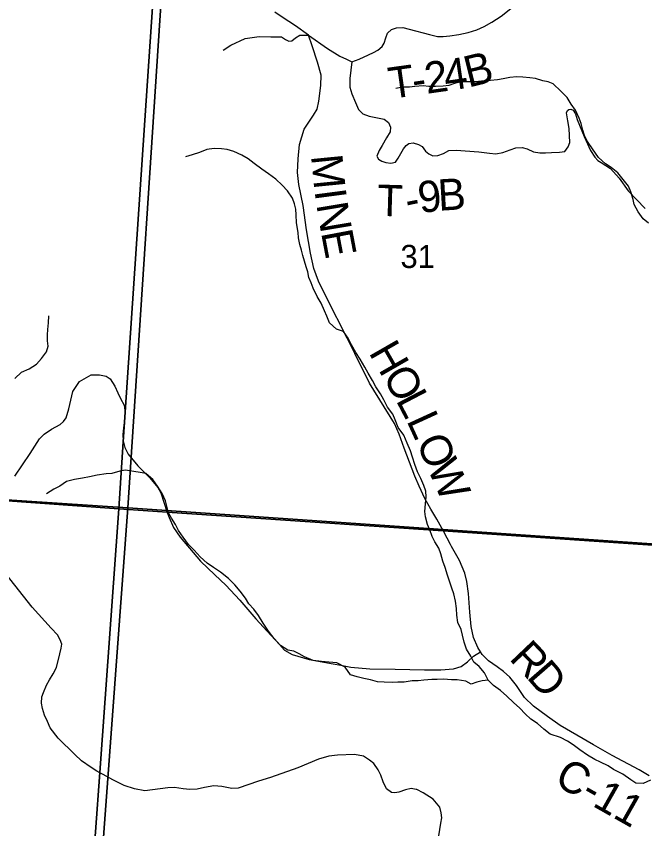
# Model space of a CAD drawing. Extents: x 0 to 34, y 0 to 22.
# Drawn here: x 5.215 to 6.354, y 18.398 to 19.87 of the extents above; entities that cross this region are included whole.
import ezdxf

# ---------------------------------------------------------------- set-up
doc = ezdxf.new("R2010")
doc.units = 0
for name, color, linetype in [('GM_X_County_Road', 7, 'Continuous'), ('GM_X_County_Road_Text', 7, 'Continuous'), ('GM_X_Minor_River', 7, 'Continuous'), ('GM_X_Section', 7, 'Continuous'), ('GM_X_Section_Text', 7, 'Continuous'), ('GM_X_Township_Road', 7, 'Continuous'), ('GM_X_Township_Road_Text', 7, 'Continuous'), ('SC_Scratch1', 7, 'Continuous')]:
    doc.layers.add(name, color=color, linetype=linetype)

msp = doc.modelspace()

# ---------------------------------------------------------------- linework, layer by layer
at = {"layer": 'GM_X_County_Road'}
for points in [[(6.004, 18.9092), (6.0019, 18.9128), (5.9897, 18.936), (5.9891, 18.9372), (5.9772, 18.959), (5.9665, 18.9773), (5.9554, 18.9966), (5.945, 19.0186), (5.9377, 19.0366), (5.9181, 19.0877), (5.909, 19.1128), (5.9007, 19.1324), (5.8554, 19.2052), (5.8285, 19.2593), (5.815, 19.2872), (5.7777, 19.3593), (5.7627, 19.3902), (5.7542, 19.4132), (5.748, 19.4412), (5.7413, 19.4832), (5.7352, 19.5276), (5.7273, 19.5658), (5.7249, 19.5875), (5.726, 19.6123), (5.7281, 19.6381), (5.7324, 19.6521), (5.7368, 19.6661), (5.7441, 19.677), (5.7536, 19.6912), (5.7603, 19.7022), (5.7631, 19.7163), (5.767, 19.7447), (5.7679, 19.7637), (5.7609, 19.7873), (5.7511, 19.8166), (5.7444, 19.8362), (5.7211, 19.853), (5.6967, 19.8686), (5.6838, 19.8781)], [(6.362, 18.4937), (6.3442, 18.5044), (6.2953, 18.5307), (6.2616, 18.5497), (6.2008, 18.5852), (6.1781, 18.6011), (6.1527, 18.62), (6.1365, 18.6359), (6.1215, 18.6577), (6.1096, 18.6727), (6.0983, 18.6831), (6.0867, 18.6916), (6.0711, 18.7023), (6.0594, 18.7136), (6.0565, 18.7184), (6.0515, 18.7265), (6.0438, 18.7442), (6.0396, 18.7647), (6.0371, 18.7907), (6.0347, 18.8244), (6.0319, 18.8458), (6.0279, 18.8611), (6.0181, 18.884), (6.004, 18.9092)]]:
    msp.add_lwpolyline(points, dxfattribs=at)
at = {"layer": 'GM_X_Minor_River'}
for points in [[(6.2136, 19.7235), (6.2018, 19.7348), (6.1885, 19.7477), (6.179, 19.7515), (6.1692, 19.7537), (6.1563, 19.7579), (6.1457, 19.7586), (6.1332, 19.7601), (6.1226, 19.7608), (6.1097, 19.7596), (6.0976, 19.757), (6.0874, 19.7554), (6.0745, 19.7542), (6.0636, 19.7535), (6.0526, 19.7523), (6.0424, 19.7519), (6.0318, 19.7515), (6.0216, 19.7515), (6.0095, 19.7488), (5.9989, 19.745), (5.9887, 19.7438), (5.975, 19.7434), (5.9625, 19.7434), (5.9523, 19.7441), (5.9376, 19.7429), (5.9277, 19.7418), (5.9152, 19.7417), (5.9027, 19.7398)], [(6.3608, 19.4953), (6.3513, 19.5032), (6.3422, 19.5157), (6.3349, 19.529), (6.333, 19.5384), (6.3288, 19.5525), (6.3246, 19.5623), (6.3151, 19.5744), (6.3052, 19.5865), (6.2931, 19.5963), (6.2832, 19.6031), (6.2703, 19.6145), (6.2593, 19.63), (6.2505, 19.6432), (6.2452, 19.6546), (6.2422, 19.6641), (6.2391, 19.6762), (6.2356, 19.686), (6.2284, 19.7004), (6.2208, 19.7114), (6.2136, 19.7235)], [(5.8879, 19.1617), (5.8811, 19.1753), (5.875, 19.1859), (5.867, 19.1991), (5.8609, 19.2101), (5.8529, 19.2234), (5.8468, 19.2347), (5.8384, 19.2487), (5.8305, 19.2612), (5.8225, 19.2752), (5.8167, 19.2873), (5.808, 19.2991), (5.7955, 19.3036), (5.7826, 19.3146), (5.7776, 19.3267), (5.7738, 19.3365), (5.7673, 19.3505), (5.7601, 19.3626), (5.7529, 19.3778), (5.7494, 19.3873), (5.7452, 19.3971), (5.7433, 19.407), (5.7406, 19.4164), (5.7372, 19.4263), (5.7345, 19.4369), (5.7318, 19.4464), (5.7291, 19.457), (5.7268, 19.4687), (5.726, 19.4786), (5.723, 19.496), (5.7222, 19.5108), (5.7214, 19.5206), (5.7191, 19.5305), (5.7156, 19.5407), (5.7065, 19.554), (5.6966, 19.5645), (5.6856, 19.5755), (5.6719, 19.5846), (5.6598, 19.5933), (5.6461, 19.6035), (5.6355, 19.6118), (5.6238, 19.6186), (5.6094, 19.6254), (5.5972, 19.6287), (5.587, 19.6302), (5.5734, 19.631), (5.5605, 19.629), (5.5469, 19.6233), (5.5337, 19.6195), (5.5216, 19.6157)], [(5.2125, 19.2142), (5.2245, 19.2252), (5.2381, 19.2313), (5.2514, 19.2397), (5.2608, 19.2503), (5.2695, 19.2625), (5.2728, 19.2727), (5.2717, 19.2822), (5.2716, 19.2928), (5.272, 19.3027), (5.2735, 19.3148), (5.2738, 19.3277)], [(6.3648, 18.4857), (6.3516, 18.48), (6.3383, 18.4807), (6.3288, 18.4867), (6.3148, 18.4966), (6.2974, 18.5052), (6.2879, 18.512), (6.2739, 18.5185), (6.2636, 18.5234), (6.2503, 18.5313), (6.2363, 18.5407), (6.2242, 18.5498), (6.2143, 18.5566), (6.2014, 18.563), (6.1828, 18.5694), (6.1715, 18.5781), (6.1597, 18.5887), (6.1475, 18.5966), (6.1377, 18.6061), (6.1278, 18.6163), (6.1164, 18.6269), (6.1039, 18.6379), (6.0925, 18.6484), (6.0803, 18.6575), (6.0701, 18.667), (6.0636, 18.6806), (6.0541, 18.6919), (6.0446, 18.6999), (6.0389, 18.7109), (6.0313, 18.7234), (6.0267, 18.7362), (6.0236, 18.7487), (6.0213, 18.759), (6.0152, 18.7719), (6.0137, 18.7851), (6.0129, 18.7972), (6.011, 18.8101), (6.0079, 18.8234), (6.0044, 18.8336), (5.9964, 18.8575), (5.9922, 18.8715), (5.9884, 18.8829), (5.9846, 18.8961), (5.9807, 18.9064), (5.9739, 18.9177), (5.9689, 18.9276), (5.9644, 18.9397), (5.9605, 18.9495), (5.9567, 18.9632), (5.9555, 18.973), (5.9566, 18.9867), (5.9581, 18.9996), (5.9573, 19.0098), (5.9539, 19.02), (5.9482, 19.0325), (5.9424, 19.0446), (5.9375, 19.0583), (5.9333, 19.0712), (5.9298, 19.0829), (5.9237, 19.0965), (5.9172, 19.1113), (5.907, 19.1249), (5.902, 19.1393), (5.8974, 19.1492), (5.8879, 19.1617)], [(6.0701, 18.667), (6.0595, 18.6662), (6.0497, 18.6635), (6.0395, 18.6601), (6.0296, 18.6653), (6.0141, 18.6676), (6.0038, 18.6679), (5.9891, 18.6687), (5.9781, 18.6686), (5.9683, 18.6682), (5.9539, 18.6671), (5.9433, 18.6659), (5.9327, 18.6659), (5.9183, 18.6636), (5.9066, 18.6635), (5.8964, 18.6627), (5.882, 18.6635), (5.8699, 18.6642), (5.857, 18.6676), (5.8449, 18.6702), (5.8327, 18.6732), (5.8206, 18.677), (5.8111, 18.691), (5.7959, 18.6985), (5.7812, 18.6996), (5.7683, 18.7011), (5.7528, 18.703), (5.7376, 18.7094), (5.7277, 18.7146), (5.7183, 18.7199), (5.7069, 18.7214), (5.694, 18.7297), (5.6826, 18.7426), (5.6723, 18.7562), (5.6625, 18.7702), (5.6541, 18.7842), (5.6457, 18.7956), (5.6362, 18.8058), (5.6305, 18.8156), (5.6206, 18.8285), (5.6111, 18.8402), (5.5997, 18.8516), (5.5853, 18.8629), (5.5724, 18.8716), (5.5607, 18.8792), (5.5485, 18.8905), (5.5375, 18.903), (5.5272, 18.9128), (5.5174, 18.9261), (5.509, 18.9382), (5.5036, 18.9492), (5.496, 18.9605), (5.4907, 18.9707), (5.4884, 18.9802), (5.4853, 18.992), (5.4796, 19.0052), (5.4709, 19.0185), (5.4625, 19.0309), (5.45, 19.0419), (5.4397, 19.0438), (5.428, 19.0456), (5.4129, 19.0475), (5.4023, 19.046), (5.3883, 19.0418), (5.3777, 19.0414), (5.3618, 19.0387), (5.3474, 19.0356), (5.3349, 19.0333), (5.3202, 19.0306), (5.3058, 19.0275), (5.2937, 19.0188), (5.2828, 19.0134), (5.2699, 19.0051)]]:
    msp.add_lwpolyline(points, dxfattribs=at)
at = {"layer": 'GM_X_Section'}
for points in [[(4.4687, 20.0485), (5.483, 19.983), (5.4174, 18.9797), (4.4009, 19.0464)], [(6.465, 19.9265), (6.4104, 18.9115), (5.4174, 18.9797), (5.483, 19.983)], [(4.3808, 19.0475), (4.4009, 19.0464), (5.4174, 18.9797), (5.3412, 17.9492), (4.3187, 18.0057)], [(5.4174, 18.9797), (6.4104, 18.9115), (6.3391, 17.8836), (5.3412, 17.9492)]]:
    msp.add_lwpolyline(points, close=True, dxfattribs=at)
at = {"layer": 'GM_X_Township_Road'}
for points in [[(5.823, 19.7879), (5.8362, 19.7928), (5.8536, 19.8007), (5.8625, 19.805), (5.8704, 19.8093), (5.8784, 19.8154), (5.882, 19.8218), (5.8848, 19.8313), (5.8878, 19.8396), (5.8952, 19.8463), (5.9044, 19.8494), (5.9154, 19.85), (5.927, 19.8472), (5.964, 19.8377), (5.9787, 19.8338), (5.9885, 19.8335), (6.0007, 19.835), (6.0172, 19.8377), (6.0338, 19.8408), (6.0497, 19.8457), (6.0631, 19.8521), (6.0772, 19.8598), (6.094, 19.8705), (6.1114, 19.8845)], [(5.5899, 19.8091), (5.604, 19.818), (5.6301, 19.83), (5.655, 19.8336), (5.6765, 19.833), (5.6955, 19.8333), (5.7031, 19.8283), (5.7087, 19.8254), (5.7146, 19.826), (5.721, 19.8312), (5.7287, 19.8364), (5.7444, 19.8362)], [(5.7444, 19.8362), (5.7793, 19.8123), (5.8016, 19.798), (5.8138, 19.7925), (5.823, 19.7879), (5.8193, 19.7576), (5.8193, 19.7417), (5.8233, 19.7301), (5.8297, 19.7142), (5.8355, 19.7013), (5.8429, 19.6934), (5.8548, 19.6894), (5.8698, 19.6866), (5.882, 19.6839), (5.8894, 19.6781), (5.893, 19.6695), (5.8927, 19.6609), (5.886, 19.6499), (5.8781, 19.6365), (5.8726, 19.6273), (5.8688, 19.617), (5.8716, 19.6117), (5.8778, 19.608), (5.8851, 19.6056), (5.8937, 19.604), (5.9025, 19.6062), (5.9071, 19.6131), (5.912, 19.6217), (5.9169, 19.6303), (5.9215, 19.6365), (5.9267, 19.6398), (5.9343, 19.6411), (5.9441, 19.638), (5.9506, 19.6343), (5.957, 19.6261), (5.9628, 19.6212), (5.9698, 19.6175), (5.979, 19.6184), (5.9891, 19.6218), (5.9989, 19.627), (6.0123, 19.6279), (6.0536, 19.6248), (6.0726, 19.6221), (6.0843, 19.6211), (6.0971, 19.6236), (6.1105, 19.6282), (6.1206, 19.6322), (6.1322, 19.6328), (6.1411, 19.63), (6.1524, 19.6248), (6.1641, 19.623), (6.1745, 19.623), (6.1849, 19.6236), (6.1995, 19.6239), (6.2094, 19.6255), (6.2154, 19.6337), (6.2185, 19.6417), (6.2173, 19.6671), (6.2145, 19.6808), (6.2124, 19.6952), (6.2142, 19.6995), (6.2167, 19.7016), (6.2204, 19.7022), (6.2243, 19.7001), (6.2286, 19.6934), (6.2317, 19.6836), (6.2445, 19.6527), (6.2561, 19.6273), (6.2638, 19.6151), (6.269, 19.6092), (6.2751, 19.6053), (6.2919, 19.5943), (6.3078, 19.5768), (6.3243, 19.5542), (6.3549, 19.5218)], [(5.212, 19.037), (5.2403, 19.0778), (5.2569, 19.1043), (5.2656, 19.113), (5.2786, 19.1222), (5.2943, 19.1308), (5.3004, 19.1357), (5.3051, 19.1429), (5.3103, 19.1588), (5.3154, 19.1824), (5.3174, 19.1905), (5.3293, 19.2084), (5.3507, 19.2203), (5.3659, 19.2207), (5.3779, 19.2184), (5.3852, 19.2131), (5.3937, 19.2001), (5.3991, 19.1878), (5.4041, 19.1779), (5.4106, 19.1658), (5.4118, 19.1564), (5.4115, 19.1424), (5.4094, 19.1245), (5.4081, 19.1126), (5.4085, 19.1002), (5.4091, 19.0984), (5.4119, 19.0888), (5.4175, 19.0769), (5.4355, 19.0558), (5.4568, 19.0338), (5.4716, 19.0161), (5.4768, 19.0067), (5.4887, 18.9713), (5.4918, 18.9622), (5.5001, 18.9438), (5.5122, 18.9266), (5.5486, 18.883), (5.5751, 18.8581), (5.595, 18.8395), (5.6202, 18.8123), (5.6493, 18.7785), (5.67, 18.7562), (5.692, 18.7316), (5.7012, 18.7217), (5.7148, 18.7138), (5.7458, 18.7044), (5.7893, 18.6966), (5.8031, 18.6941)], [(5.5563, 18.4727), (5.5428, 18.4697), (5.5294, 18.4689), (5.5176, 18.4704), (5.5016, 18.4724), (5.4899, 18.4718), (5.4479, 18.4663), (5.4289, 18.4699), (5.4107, 18.4765), (5.39, 18.4864), (5.3725, 18.4961), (5.3664, 18.4994), (5.3609, 18.5023), (5.3507, 18.5086), (5.3334, 18.5211), (5.3212, 18.5323), (5.2905, 18.5622), (5.2762, 18.5806), (5.2713, 18.5924), (5.2658, 18.6039), (5.2622, 18.6155), (5.2603, 18.6256), (5.2614, 18.6368), (5.2643, 18.6449), (5.2696, 18.6579), (5.2751, 18.6676), (5.2817, 18.6786), (5.2879, 18.6903), (5.294, 18.715), (5.2965, 18.7249), (5.2973, 18.7323), (5.2946, 18.7405), (5.2893, 18.7492), (5.2783, 18.7612), (5.2439, 18.7997), (5.1968, 18.8592)], [(5.8031, 18.6941), (5.8214, 18.6907), (5.8558, 18.6878), (5.902, 18.6871), (5.955, 18.686), (5.9848, 18.6858), (6.0077, 18.6876), (6.0214, 18.6921), (6.0326, 18.7006), (6.0438, 18.7105), (6.0565, 18.7184)], [(5.9397, 18.4689), (5.9308, 18.4708), (5.9207, 18.4682), (5.9087, 18.4642), (5.9014, 18.463), (5.8949, 18.4638), (5.886, 18.4699), (5.8801, 18.4826), (5.8759, 18.4951), (5.871, 18.5046), (5.8632, 18.516), (5.8554, 18.5223), (5.8444, 18.5293), (5.8281, 18.5325), (5.7975, 18.531), (5.7815, 18.5295), (5.7626, 18.5238), (5.725, 18.508), (5.676, 18.4908), (5.6541, 18.4843), (5.6173, 18.4716), (5.6059, 18.4706), (5.5875, 18.4742), (5.5732, 18.4754), (5.5563, 18.4727)], [(5.9811, 18.3852), (5.9844, 18.408), (5.9863, 18.4176), (5.9853, 18.4264), (5.9825, 18.437), (5.9709, 18.4516), (5.9526, 18.4632), (5.9409, 18.4687), (5.9397, 18.4689)]]:
    msp.add_lwpolyline(points, dxfattribs=at)
at = {"layer": 'SC_Scratch1'}
for points in [[(5.53, 20.9), (2.1, 20.9), (2.1, 19.1982), (2.3572, 19.1804), (3.3448, 19.1146), (4.3628, 19.0495), (4.7394, 19.0241), (4.7997, 19.0196), (5.182, 18.9932), (5.4007, 18.9779), (5.4089, 19.0989), (5.4469, 19.6641), (5.4955, 20.3864)], [(8.9, 18.7389), (8.9, 20.9), (5.53, 20.9), (5.4955, 20.3864), (5.4469, 19.6641), (5.4089, 19.0989), (5.4007, 18.9779), (5.4885, 18.9719), (5.9889, 18.9377), (6.8273, 18.8804), (7.2159, 18.8539), (8.2061, 18.7863)], [(2.1, 19.1982), (2.1, 14.1), (5.0535, 14.1), (5.0814, 14.5016), (5.1049, 14.8414), (5.1794, 15.9156), (5.2761, 17.2534), (5.2869, 17.4026), (5.3506, 18.2846), (5.3662, 18.4999), (5.4007, 18.9779), (5.182, 18.9932), (4.7997, 19.0196), (4.7394, 19.0241), (4.3628, 19.0495), (3.3448, 19.1146), (2.3572, 19.1804)], [(5.0535, 14.1), (8.9, 14.1), (8.9, 18.7389), (8.2061, 18.7863), (7.2159, 18.8539), (6.8273, 18.8804), (5.9889, 18.9377), (5.4885, 18.9719), (5.4007, 18.9779), (5.3662, 18.4999), (5.3506, 18.2846), (5.2869, 17.4026), (5.2761, 17.2534), (5.1794, 15.9156), (5.1049, 14.8414), (5.0814, 14.5016)]]:
    msp.add_lwpolyline(points, close=True, dxfattribs=at)

# ---------------------------------------------------------------- texts
at = {"layer": 'GM_X_County_Road_Text'}
for s, height, rotation, p in [('M', 0.0568, 275.6268, (5.7491, 19.6178)), ('I', 0.0568, 277.4871, (5.7554, 19.5545)), ('N', 0.0568, 279.4602, (5.7587, 19.5293)), ('E', 0.0568, 280.7354, (5.7672, 19.4786)), ('H', 0.0568, 299.8741, (5.8529, 19.2611)), ('O', 0.0568, 299.763, (5.8778, 19.2177)), ('L', 0.0568, 297.6096, (5.9023, 19.1748)), ('L', 0.0568, 294.5944, (5.9217, 19.1379)), ('O', 0.0568, 293.0489, (5.9392, 19.0996)), ('W', 0.0568, 293.7523, (5.9591, 19.0529)), ('R', 0.0568, 313.6254, (6.1068, 18.7054)), ('D', 0.0568, 310.968, (6.1386, 18.6721)), ('C-11', 0.05682, 330.5374, (6.1877, 18.4795))]:
    msp.add_text(s, height=height, rotation=rotation, dxfattribs=at).set_placement(p)
at = {"layer": 'GM_X_Section_Text'}
msp.add_text('31', height=0.04186, rotation=0, dxfattribs=at).set_placement((5.9114, 19.4142))
at = {"layer": 'GM_X_Township_Road_Text'}
for s, rotation, p in [('4', 8.2578, (5.9938, 19.7347)), ('B', 13.874, (6.0344, 19.7409)), ('T', 8.001, (5.8937, 19.7206)), ('2', 8.0642, (5.959, 19.7298)), ('-', 8.0129, (5.9358, 19.7265)), ('9', 7.6995, (5.947, 19.5133)), ('B', 3.3509, (5.9806, 19.5179)), ('T', 358.307, (5.8684, 19.5088)), ('-', 11.651, (5.9252, 19.5088))]:
    msp.add_text(s, height=0.0568, rotation=rotation, dxfattribs=at).set_placement(p)

doc.saveas('drawing.dxf')
